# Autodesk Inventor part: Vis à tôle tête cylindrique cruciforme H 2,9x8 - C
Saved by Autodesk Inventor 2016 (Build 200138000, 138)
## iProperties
Created: 2003-09
Part Number: Vis à tôle tête cylindrique cruciforme H 2,9x8 - C
Material: Générique
Document SubType Name: Modeling
Designer: Bruno
Density: 1 g/cm^3
Appearance: Par défaut
Author: Bruno
Sending System: SolidWorks 2013
Last Author: christophe
Last Saved: 2014-02-15
SwCadDb Education & Formation: v2
Swc_Composant: Vis à tête cylindrique cruciforme H (Philips)
Diamètre nominal: 2,9
Longueur sous tête: 13
Diamètre extérieur: 2,9
Diamètre noyau: 2,18
Pas du filetage: 1
Swc_Designation: Vis à tôle tête cylindrique cruciforme H 2,9x13 - C
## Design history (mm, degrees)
feature "Boss.-Balayage7"
node "Solide1"
